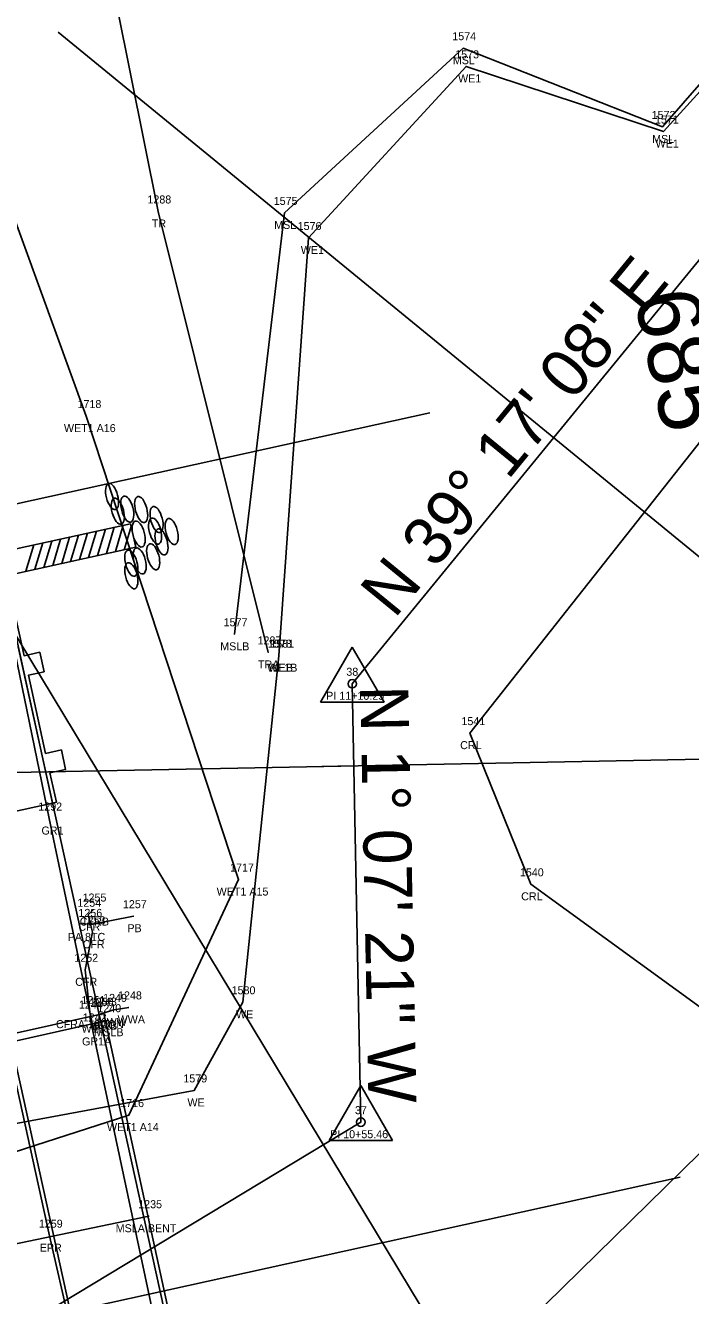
# Model space of a CAD drawing. Extents: x 2522090 to 2524658, y 882711 to 887512.
# Drawn here: x 2523795.3 to 2523878.4, y 885126.7 to 885285.4 of the extents above; entities that cross this region are included whole.
import ezdxf

# ---------------------------------------------------------------- set-up
doc = ezdxf.new("R2010")
doc.units = 0
for name, color, linetype in [('RD_EV_JurisArea', 7, 'Continuous'), ('RD_EX_BldgApp', 7, 'Continuous'), ('RD_EX_BldgApp_txCode', 7, 'Continuous'), ('RD_EX_Bridge', 7, 'Continuous'), ('RD_EX_Bridge_txCode', 7, 'Continuous'), ('RD_EX_Conc', 7, 'Continuous'), ('RD_EX_Conc_txCode', 7, 'Continuous'), ('RD_EX_DR_Pipe', 7, 'Continuous'), ('RD_EX_DR_Pipe_txCode', 7, 'Continuous'), ('RD_EX_GuardRail', 7, 'Continuous'), ('RD_EX_GuardRail_txCode', 7, 'Continuous'), ('RD_EX_H2O', 7, 'Continuous'), ('RD_EX_H2O_txCode', 7, 'Continuous'), ('RD_EX_H2O_WetLd_txCode', 7, 'Continuous'), ('RD_EX_Misc', 7, 'Continuous'), ('RD_EX_Misc_txCode', 7, 'Continuous'), ('RD_EX_Road', 7, 'Continuous'), ('RD_EX_Road_txCode', 7, 'Continuous'), ('RD_EX_VEG', 7, 'Continuous'), ('RD_EX_VEG_txCode', 7, 'Continuous'), ('RD_HC_Cl', 7, 'Continuous'), ('RD_HC_Data', 7, 'Continuous'), ('RD_HC_Data_Tic', 7, 'Continuous'), ('RD_HC_TX_Sta50', 7, 'Continuous'), ('RD_HC_txCode', 7, 'Continuous'), ('RD_PD_Bridge', 7, 'Continuous'), ('RD_PD_Final_TrvlWay', 7, 'Continuous'), ('RD_PD_GR', 7, 'Continuous'), ('RD_PD_PatLn5', 7, 'Continuous'), ('RD_PD_PatLn6', 7, 'Continuous'), ('RD_PD_PaveShd', 7, 'Continuous'), ('RD_SMD_Locator', 7, 'Continuous')]:
    doc.layers.add(name, color=color, linetype=linetype)

# ---------------------------------------------------------------- blocks, each defined once
blk = doc.blocks.new('TBC1')
at = {"layer": 'RD_PD_GR'}
blk.add_lwpolyline([(12.5, 2.5), (15, 2.5), (15, 0.49), (25, 0.49), (25, 2.5), (27.5, 2.5), (27.5, 0.49), (31.25, 0.49), (31.25, 0), (0, 0), (0, 0.49), (12.5, 0.49)], close=True, dxfattribs=at)

msp = doc.modelspace()

# ---------------------------------------------------------------- linework, layer by layer
at = {"layer": 'RD_EV_JurisArea'}
msp.add_lwpolyline([(2523761.17, 885134.03), (2523808.21, 885149.21), (2523821.91, 885178.64), (2523802.85, 885236.55), (2523777.81, 885305.56), (2523748.2, 885444.32), (2523730.68, 885516.88), (2523708.64, 885617.3), (2523698.71, 885662.02), (2523727.83, 885665.82), (2523757.3, 885671.75)], dxfattribs=at)
at = {"layer": 'RD_EX_BldgApp'}
msp.add_lwpolyline([(2523819.44, 885087.44), (2523811.32, 885123.96), (2523803.31, 885161.5)], dxfattribs=at)
at = {"layer": 'RD_EX_Bridge'}
for points in [[(2523774.91, 885077.6), (2523821.2, 885087.83), (2523805.06, 885161.89), (2523758.15, 885151.44), (2523774.91, 885077.6)], [(2523808.19, 885162.66), (2523806.34, 885162.35), (2523804.71, 885161.86)]]:
    msp.add_lwpolyline(points, dxfattribs=at)
at = {"layer": 'RD_EX_Conc'}
msp.add_lwpolyline([(2523803.34, 885162.07), (2523802.73, 885167.36), (2523803.65, 885172.05), (2523803.12, 885174.24), (2523803.77, 885174.89)], dxfattribs=at)
at = {"layer": 'RD_EX_DR_Pipe'}
msp.add_line((2523803.27, 885172.97), (2523808.8, 885174.06), dxfattribs=at)
at = {"layer": 'RD_EX_GuardRail'}
msp.add_lwpolyline([(2523803.79, 885159.91), (2523798.24, 885186.26), (2523787.8, 885236.89)], dxfattribs=at)
at = {"layer": 'RD_EX_H2O'}
for points in [[(2524064.86, 885165.15), (2524036.37, 885213.78), (2524057.22, 885252.72), (2524031.95, 885291.63), (2523983.25, 885326.3), (2523940.61, 885311.83), (2523904.84, 885305.01), (2523874.98, 885272.1), (2523850.32, 885280.24), (2523830.66, 885258.8), (2523826.93, 885206.61)], [(2523582.82, 884766.34), (2523598.11, 884856.98), (2523627.59, 884901.75), (2523623.76, 884928.28), (2523586.58, 884955.43), (2523600.94, 884974.12), (2523633.05, 884997.68), (2523679.17, 885037.05), (2523744.72, 885076.89), (2523769.38, 885099), (2523825.47, 885108.66), (2523825.47, 885108.66), (2523845.24, 885110.83), (2523890.25, 885154.93), (2523858.43, 885178.04), (2523850.81, 885196.93), (2523892.51, 885249.74), (2523936.89, 885290.09), (2523980.86, 885285.47), (2524009.06, 885269.77), (2524037.39, 885280.09)], [(2523738.91, 885147.5), (2523743.69, 885138.84), (2523816.36, 885152.29), (2523822.43, 885163.3), (2523826.93, 885206.61)]]:
    msp.add_lwpolyline(points, dxfattribs=at)
at = {"layer": 'RD_EX_Misc'}
for p, q in [((2523758.45, 885150.47), (2523805.66, 885161.06)), ((2523810.71, 885136.57), (2523763.83, 885126.8))]:
    msp.add_line(p, q, dxfattribs=at)
msp.add_lwpolyline([(2524066.31, 885165.35), (2524037.3, 885214.15), (2524057.95, 885253.07), (2524039.52, 885283.17), (2524032.92, 885292.57), (2523983.53, 885327.98), (2523940.24, 885313.27), (2523904.13, 885306.25), (2523874.86, 885272.67), (2523849.96, 885282.51), (2523827.65, 885261.93), (2523821.38, 885209.28)], dxfattribs=at)
at = {"layer": 'RD_EX_Road'}
for p, q in [((2523798.3, 885134.14), (2523792.89, 885158.83)), ((2523803.79, 885109.94), (2523798.3, 885134.14))]:
    msp.add_line(p, q, dxfattribs=at)
at = {"layer": 'RD_EX_VEG'}
msp.add_lwpolyline([(2523825.62, 885207.01), (2523811.87, 885262.11), (2523733.02, 885654.22), (2523687.11, 885876.24)], dxfattribs=at)
at = {"layer": 'RD_HC_Cl'}
for p, q in [((2523836.11, 885203.1), (2523883.66, 885261.23)), ((2523837.18, 885148.32), (2523836.11, 885203.1)), ((2523672.04, 885048.63), (2523837.18, 885148.32))]:
    msp.add_line(p, q, dxfattribs=at)
at = {"layer": 'RD_HC_Data'}
for p, q in [((2523832.14, 885200.81), (2523836.11, 885207.69)), ((2523836.11, 885207.69), (2523840.08, 885200.81)), ((2523832.14, 885200.81), (2523840.08, 885200.81)), ((2523833.21, 885146.03), (2523837.18, 885152.91)), ((2523837.18, 885152.91), (2523841.15, 885146.03)), ((2523833.21, 885146.03), (2523841.15, 885146.03))]:
    msp.add_line(p, q, dxfattribs=at)
for centre in [(2523836.11, 885203.1), (2523837.18, 885148.32)]:
    msp.add_circle(centre, 0.529, dxfattribs=at)
at = {"layer": 'RD_HC_Data_Tic'}
msp.add_line((2523836.31, 885192.84), (2523832.31, 885192.77), dxfattribs=at)
at = {"layer": 'RD_PD_Bridge'}
for points in [[(2523830.93, 885041.7), (2523794.37, 885207.73)], [(2523798.67, 885188.19), (2523752.77, 885178.09)]]:
    msp.add_lwpolyline(points, dxfattribs=at)
at = {"layer": 'RD_PD_Final_TrvlWay'}
msp.add_line((2523722.39, 885481.14), (2524037.44, 884050.42), dxfattribs=at)
at = {"layer": 'RD_PD_PatLn5'}
for p, q in [((2523845.79, 885236.96), (2523689.53, 885202.56)), ((2523877.06, 885141.45), (2523711.04, 885104.9))]:
    msp.add_line(p, q, dxfattribs=at)
at = {"layer": 'RD_PD_PatLn6'}
for p, q in [((2523799.35, 885284.52), (2523923.19, 885183.21)), ((2523791.15, 885213.98), (2523873.84, 885077.01)), ((2523756.32, 885191.28), (2523916.29, 885194.41))]:
    msp.add_line(p, q, dxfattribs=at)
at = {"layer": 'RD_PD_PaveShd'}
for p, q in [((2523792.77, 885219.66), (2523808.42, 885223.1)), ((2523800.93, 885218.38), (2523801.91, 885221.67)), ((2523800.93, 885218.38), (2523801.91, 885221.67)), ((2523802.05, 885218.63), (2523803.03, 885221.91)), ((2523802.05, 885218.63), (2523803.03, 885221.91)), ((2523803.17, 885218.87), (2523804.15, 885222.16)), ((2523803.17, 885218.87), (2523804.15, 885222.16)), ((2523804.28, 885219.12), (2523805.27, 885222.4)), ((2523804.28, 885219.12), (2523805.27, 885222.4)), ((2523805.4, 885219.36), (2523806.38, 885222.65)), ((2523805.4, 885219.36), (2523806.38, 885222.65)), ((2523806.52, 885219.61), (2523807.5, 885222.9)), ((2523806.52, 885219.61), (2523807.5, 885222.9)), ((2523807.63, 885219.85), (2523808.5, 885222.74)), ((2523807.63, 885219.85), (2523808.5, 885222.74)), ((2523808.42, 885223.1), (2523809.06, 885220.17)), ((2523808.42, 885223.1), (2523809.06, 885220.17)), ((2523809.06, 885220.17), (2523793.41, 885216.73)), ((2523795.34, 885217.15), (2523796.33, 885220.44)), ((2523795.34, 885217.15), (2523796.33, 885220.44)), ((2523796.46, 885217.4), (2523797.45, 885220.69)), ((2523796.46, 885217.4), (2523797.45, 885220.69)), ((2523797.58, 885217.64), (2523798.56, 885220.93)), ((2523797.58, 885217.64), (2523798.56, 885220.93)), ((2523798.7, 885217.89), (2523799.68, 885221.18)), ((2523798.7, 885217.89), (2523799.68, 885221.18)), ((2523799.81, 885218.14), (2523800.8, 885221.42)), ((2523799.81, 885218.14), (2523800.8, 885221.42))]:
    msp.add_line(p, q, dxfattribs=at)
for centre in [(2523806.1, 885226.5), (2523808, 885224.92), (2523808, 885224.92), (2523809.74, 885224.87), (2523809.74, 885224.87), (2523806.82, 885224.65), (2523811.66, 885223.62), (2523811.66, 885223.62), (2523809.43, 885221.81), (2523809.43, 885221.81), (2523811.48, 885222.18), (2523811.48, 885222.18), (2523813.55, 885222.12), (2523813.55, 885222.12), (2523812.28, 885220.83), (2523812.28, 885220.83), (2523809.55, 885218.44), (2523809.55, 885218.44), (2523811.24, 885218.97), (2523811.24, 885218.97), (2523808.5, 885218.17), (2523808.5, 885218.17), (2523808.51, 885216.6), (2523808.51, 885216.6)]:
    msp.add_ellipse(centre, major_axis=(-0.43, 1.62), ratio=0.429445, dxfattribs=at)
at = {"layer": 'RD_SMD_Locator'}
for centre in [(2523849.96, 885282.51), (2523850.32, 885280.24), (2523874.86, 885272.67), (2523874.98, 885272.1), (2523811.87, 885262.11), (2523827.65, 885261.93), (2523830.66, 885258.8), (2523802.85, 885236.55), (2523821.38, 885209.28), (2523825.62, 885207.01), (2523826.93, 885206.61), (2523826.93, 885206.61), (2523836.11, 885203.1), (2523850.81, 885196.93), (2523798.24, 885186.26), (2523821.91, 885178.64), (2523858.43, 885178.04), (2523803.12, 885174.24), (2523803.77, 885174.89), (2523808.8, 885174.06), (2523803.27, 885172.97), (2523803.65, 885172.05), (2523802.73, 885167.36), (2523822.43, 885163.3), (2523803.31, 885161.5), (2523803.34, 885162.07), (2523804.71, 885161.86), (2523805.06, 885161.89), (2523806.34, 885162.35), (2523808.19, 885162.66), (2523803.79, 885159.91), (2523805.66, 885161.06), (2523816.36, 885152.29), (2523808.21, 885149.21), (2523837.18, 885148.32), (2523810.71, 885136.57), (2523798.3, 885134.14)]:
    msp.add_circle(centre, 0.001, dxfattribs=at)

# ---------------------------------------------------------------- block references
at = {"layer": 'RD_PD_Bridge', "rotation": -77.58151740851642}
msp.add_blockref('TBC1', (2523791.95, 885218.71), dxfattribs=at)

# ---------------------------------------------------------------- texts
at = {"layer": 'RD_EX_BldgApp_txCode'}
for s, p in [('1244', (2523801.96, 885162.5)), ('W1B', (2523802.3, 885159.5))]:
    msp.add_text(s, height=1, dxfattribs=at).set_placement(p)
at = {"layer": 'RD_EX_Bridge_txCode'}
for s, p in [('1248', (2523806.85, 885163.66)), ('1250', (2523803.32, 885162.86)), ('1243', (2523803.72, 885162.89)), ('1249', (2523804.99, 885163.35)), ('WW', (2523805.43, 885160.35)), ('WWA', (2523806.8, 885160.66)), ('WWB', (2523803.33, 885159.86)), ('BRC', (2523803.81, 885159.89))]:
    msp.add_text(s, height=1, dxfattribs=at).set_placement(p)
at = {"layer": 'RD_EX_Conc_txCode'}
for s, p in [('1254', (2523801.77, 885175.24)), ('1255', (2523802.42, 885175.89)), ('1253', (2523802.3, 885173.05)), ('CFR', (2523801.89, 885172.24)), ('CFRB', (2523802.07, 885172.89)), ('CFR', (2523802.42, 885170.05)), ('1252', (2523801.39, 885168.36)), ('CFR', (2523801.5, 885165.36)), ('1251', (2523802.28, 885163.07)), ('CFRA 18CON', (2523799.09, 885160.07))]:
    msp.add_text(s, height=1, dxfattribs=at).set_placement(p)
at = {"layer": 'RD_EX_DR_Pipe_txCode'}
for s, p in [('1257', (2523807.46, 885175.06)), ('1256', (2523801.9, 885173.97)), ('PB', (2523808.02, 885172.06)), ('PA 8TC', (2523800.57, 885170.97))]:
    msp.add_text(s, height=1, dxfattribs=at).set_placement(p)
at = {"layer": 'RD_EX_GuardRail_txCode'}
for s, p in [('1292', (2523796.89, 885187.26)), ('GR1', (2523797.29, 885184.26)), ('1242', (2523802.44, 885160.91)), ('GR1A', (2523802.35, 885157.91))]:
    msp.add_text(s, height=1, dxfattribs=at).set_placement(p)
at = {"layer": 'RD_EX_H2O_txCode'}
for s, p in [('1573', (2523848.97, 885281.24)), ('WE1', (2523849.33, 885278.24)), ('1571', (2523873.92, 885273.1)), ('WE1', (2523874, 885270.1)), ('1576', (2523829.29, 885259.8)), ('WE1', (2523829.68, 885256.8)), ('1578', (2523825.58, 885207.61)), ('1581', (2523825.87, 885207.61)), ('WE1B', (2523825.47, 885204.61)), ('WEB', (2523825.64, 885204.61)), ('1541', (2523849.75, 885197.93)), ('CRL', (2523849.59, 885194.93)), ('1540', (2523857.05, 885179.04)), ('CRL', (2523857.21, 885176.04)), ('1580', (2523821.04, 885164.3)), ('WE', (2523821.59, 885161.3)), ('1579', (2523815.01, 885153.29)), ('WE', (2523815.52, 885150.29))]:
    msp.add_text(s, height=1, dxfattribs=at).set_placement(p)
at = {"layer": 'RD_EX_H2O_WetLd_txCode'}
for s, p in [('1718', (2523801.79, 885237.55)), ('WET1 A16', (2523800.09, 885234.55)), ('1717', (2523820.85, 885179.64)), ('WET1 A15', (2523819.17, 885176.64)), ('1716', (2523807.12, 885150.21)), ('WET1 A14', (2523805.47, 885147.21))]:
    msp.add_text(s, height=1, dxfattribs=at).set_placement(p)
at = {"layer": 'RD_EX_Misc_txCode'}
for s, p in [('1574', (2523848.61, 885283.51)), ('MSL', (2523848.67, 885280.51)), ('1572', (2523873.51, 885273.67)), ('MSL', (2523873.57, 885270.67)), ('1575', (2523826.3, 885262.93)), ('MSL', (2523826.36, 885259.93)), ('1577', (2523820.04, 885210.28)), ('MSLB', (2523819.62, 885207.28)), ('1240', (2523804.27, 885162.06)), ('MSLB', (2523803.89, 885159.06)), ('1235', (2523809.37, 885137.57)), ('MSLA BENT', (2523806.56, 885134.57))]:
    msp.add_text(s, height=1, dxfattribs=at).set_placement(p)
at = {"layer": 'RD_EX_Road_txCode'}
for s, p in [('1259', (2523796.96, 885135.14)), ('EPR', (2523797.07, 885132.14))]:
    msp.add_text(s, height=1, dxfattribs=at).set_placement(p)
at = {"layer": 'RD_EX_VEG_txCode'}
for s, p in [('1288', (2523810.52, 885263.11)), ('TR', (2523811.07, 885260.11)), ('1287', (2523824.28, 885208.01)), ('TRA', (2523824.34, 885205.01))]:
    msp.add_text(s, height=1, dxfattribs=at).set_placement(p)
at = {"layer": 'RD_HC_Data'}
for s, rotation, p in [('N 39%%d 17\' 08" E', 50.7144, (2523841.39, 885211.14)), ('N 1%%d 07\' 21" W', 271.1226, (2523837.11, 885202.84))]:
    msp.add_text(s, height=6, rotation=rotation, dxfattribs=at).set_placement(p)
at = {"layer": 'RD_HC_TX_Sta50'}
msp.add_text('685', height=8, rotation=282.4185, dxfattribs=at).set_placement((2523871.26, 885251.48))
at = {"layer": 'RD_HC_txCode'}
for s, p in [('38', (2523835.37, 885204.1)), ('PI 11+10.25', (2523832.85, 885201.1)), ('37', (2523836.45, 885149.32)), ('PI 10+55.46', (2523833.34, 885146.32))]:
    msp.add_text(s, height=1, dxfattribs=at).set_placement(p)

doc.saveas('drawing.dxf')
